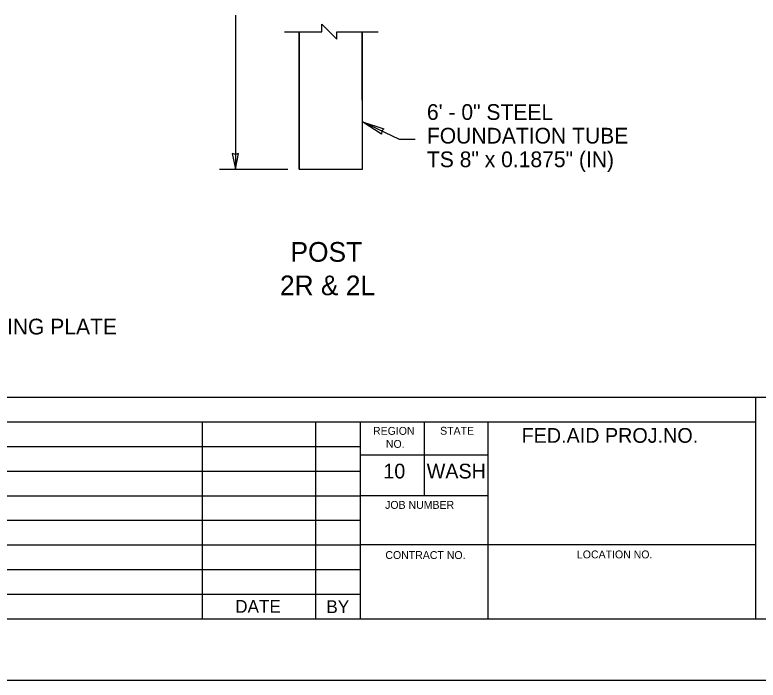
# Model space of a CAD drawing. Extents: x 1312564.2 to 1312581.5, y 1207298.4 to 1207352.6.
# Drawn here: x 1312569.104 to 1312572.883, y 1207312.821 to 1207316.204 of the extents above; entities that cross this region are included whole.
import ezdxf

# ---------------------------------------------------------------- set-up
doc = ezdxf.new("R2010")
doc.units = 0
for name, color, linetype in [('Level 1', 7, 'Continuous'), ('Level 15', 7, 'Continuous'), ('Level 2', 7, 'Continuous'), ('Level 20', 7, 'Continuous'), ('Level 3', 7, 'Continuous'), ('Level 7', 7, 'Continuous'), ('SH_GI_SheetTextInCells', 7, 'Continuous')]:
    doc.layers.add(name, color=color, linetype=linetype)

msp = doc.modelspace()

# ---------------------------------------------------------------- linework, layer by layer
at = {"layer": 'Level 1'}
for p, q in [((1312565.4155, 1207314.2593), (1312581.1655, 1207314.2593)), ((1312572.8721, 1207313.1334), (1312572.8721, 1207314.2593)), ((1312565.4155, 1207314.1342), (1312572.8721, 1207314.1342)), ((1312570.0565, 1207314.1342), (1312570.0565, 1207313.1334)), ((1312570.6319, 1207314.1342), (1312570.6319, 1207313.1334)), ((1312570.8605, 1207314.1342), (1312570.8605, 1207313.1334)), ((1312571.1874, 1207313.7589), (1312571.1874, 1207314.1342)), ((1312571.511, 1207313.1334), (1312571.511, 1207314.1342)), ((1312567.5976, 1207314.0091), (1312570.8621, 1207314.0091)), ((1312571.5112, 1207313.9644), (1312570.8621, 1207313.9644)), ((1312567.5976, 1207313.884), (1312570.8621, 1207313.884)), ((1312565.4155, 1207313.7589), (1312570.8621, 1207313.7589)), ((1312571.5112, 1207313.7589), (1312570.8621, 1207313.7589)), ((1312565.4155, 1207313.6338), (1312570.8621, 1207313.6338)), ((1312565.4155, 1207313.5087), (1312570.8621, 1207313.5087)), ((1312572.8721, 1207313.5087), (1312570.8621, 1207313.5087)), ((1312565.4155, 1207313.3836), (1312570.8621, 1207313.3836)), ((1312565.4155, 1207313.2585), (1312570.8621, 1207313.2585)), ((1312565.4155, 1207313.1334), (1312581.1655, 1207313.1334))]:
    msp.add_line(p, q, dxfattribs=at)
at = {"layer": 'Level 15'}
for p, q in [((1312570.2262, 1207316.2031), (1312570.2262, 1207315.4313)), ((1312571.059, 1207315.5709), (1312570.8715, 1207315.6612)), ((1312571.1391, 1207315.5709), (1312571.059, 1207315.5709)), ((1312570.1451, 1207315.4195), (1312570.4929, 1207315.4195))]:
    msp.add_line(p, q, dxfattribs=at)
msp.add_lwpolyline([(1312570.4751, 1207316.1189), (1312570.6642, 1207316.1189), (1312570.6642, 1207316.1577), (1312570.7417, 1207316.0801), (1312570.7417, 1207316.1189), (1312570.9508, 1207316.1189)], dxfattribs=at)
for points in [[(1312570.8715, 1207315.6612), (1312570.981, 1207315.6251), (1312570.9697, 1207315.6139), (1312570.968, 1207315.5981)], [(1312570.2252, 1207315.4199), (1312570.2406, 1207315.4987), (1312570.2252, 1207315.495), (1312570.2098, 1207315.4987)]]:
    msp.add_lwpolyline(points, close=True, dxfattribs=at)
at = {"layer": 'Level 2'}
msp.add_lwpolyline([(1312564.478, 1207312.8209), (1312581.478, 1207312.8209), (1312581.478, 1207323.8209), (1312564.478, 1207323.8209)], close=True, dxfattribs=at)
at = {"layer": 'Level 3'}
msp.add_line((1312570.5502, 1207315.4195), (1312570.8715, 1207315.4195), dxfattribs=at)
for points in [[(1312570.5502, 1207315.4195), (1312570.5502, 1207316.1189)], [(1312570.8707, 1207316.1189), (1312570.8707, 1207315.4195)]]:
    msp.add_lwpolyline(points, dxfattribs=at)
at = {"layer": 'Level 7'}
msp.add_lwpolyline([(1312570.5502, 1207316.1191), (1312570.5502, 1207315.4196), (1312570.8715, 1207315.4195), (1312570.8707, 1207316.1189)], dxfattribs=at)

# ---------------------------------------------------------------- texts
at = {"layer": 'Level 15'}
for s, p in [('POST ', (1312570.5055, 1207314.9488)), ('2R & 2L', (1312570.452, 1207314.7785))]:
    msp.add_text(s, height=0.10015, dxfattribs=at).set_placement(p)
at = {"layer": 'Level 20'}
for s, p in [('6\' - 0" STEEL ', (1312571.1992, 1207315.6701)), ('FOUNDATION TUBE ', (1312571.1992, 1207315.5499)), ('TS 8" x 0.1875" (IN)', (1312571.1992, 1207315.4297)), ('CABLE BEARING PLATE ', (1312568.391, 1207314.579))]:
    msp.add_text(s, height=0.080117, dxfattribs=at).set_placement(p)
at = {"layer": 'SH_GI_SheetTextInCells'}
for s, height, p in [('REGION', 0.04003, (1312570.9253, 1207314.0686)), ('STATE', 0.04003, (1312571.2665, 1207314.0691)), ('FED.AID PROJ.NO.', 0.07506, (1312571.6807, 1207314.0279)), ('NO.', 0.04003, (1312570.9907, 1207314.0024)), ('10', 0.07506, (1312570.9776, 1207313.8465)), ('WASH', 0.07506, (1312571.1981, 1207313.8465)), ('JOB NUMBER', 0.04003, (1312570.9867, 1207313.6921)), ('CONTRACT NO.', 0.040032, (1312570.988, 1207313.4371)), ('LOCATION NO.', 0.040032, (1312571.962, 1207313.4401)), ('DATE', 0.06505, (1312570.2246, 1207313.1634)), ('BY', 0.06505, (1312570.688, 1207313.1618))]:
    msp.add_text(s, height=height, dxfattribs=at).set_placement(p)

doc.saveas('drawing.dxf')
